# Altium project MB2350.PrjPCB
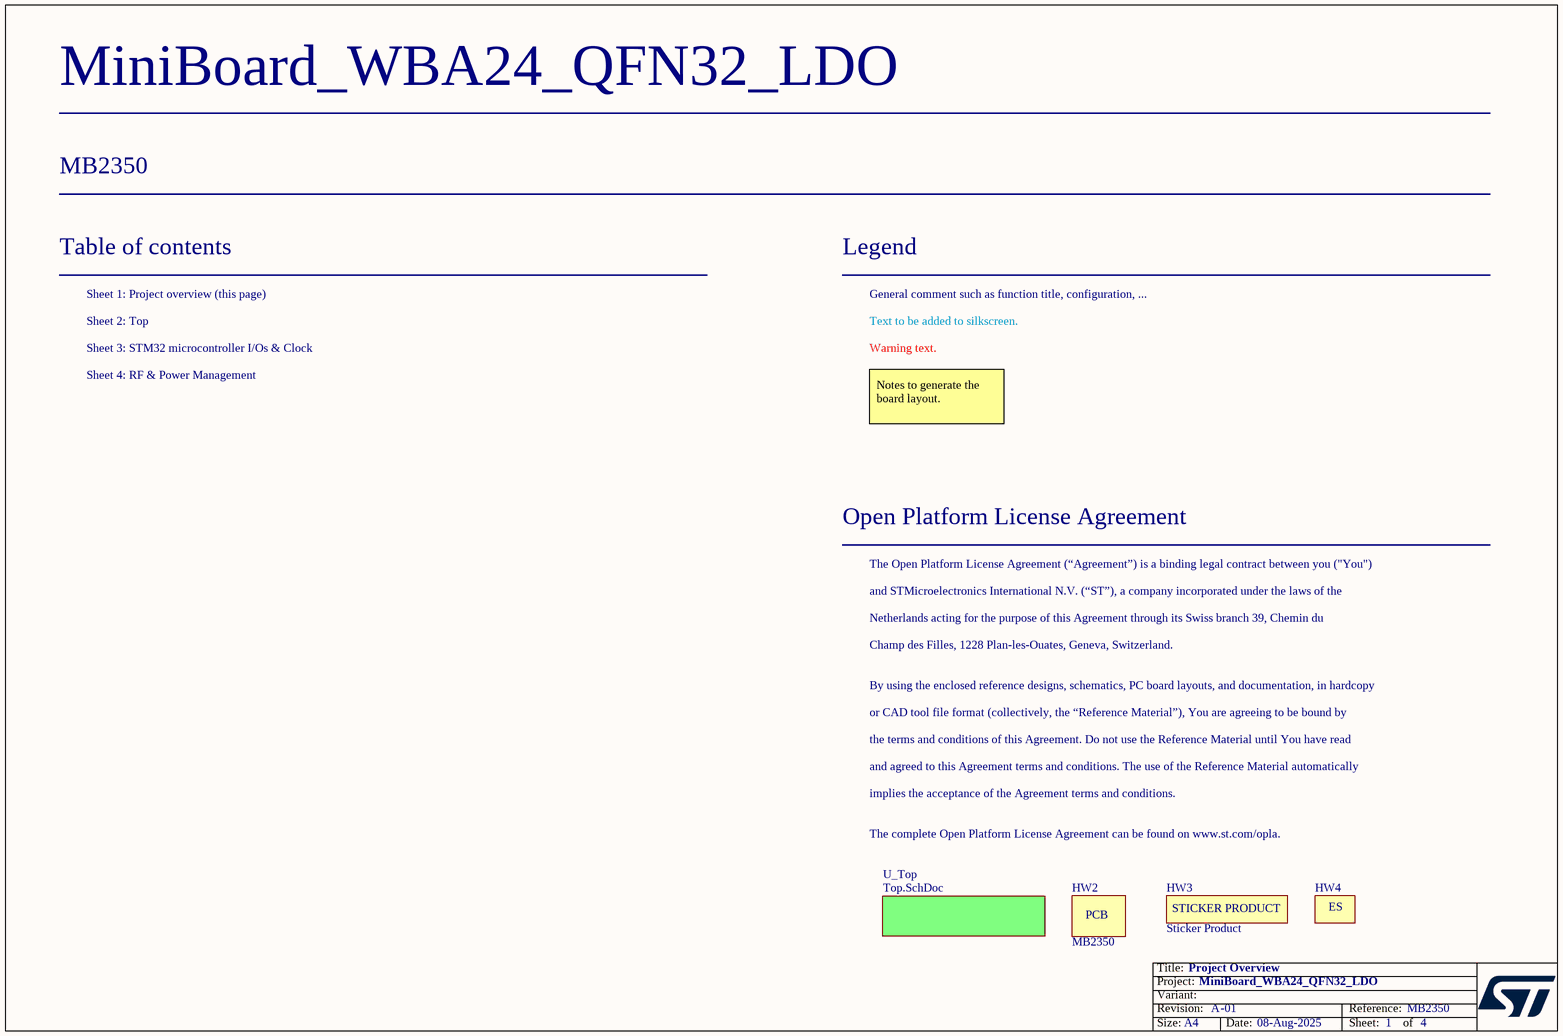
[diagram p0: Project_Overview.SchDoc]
Board_Assembly_Revision: 01; Board_Document_Date: 08-Aug-2025; Board_Name: MiniBoard_WBA24_QFN32_LDO; Board_PCB_Revision: A; Board_Reference: MB2350
4 sheets, 88 parts. Net scope: flat (ports and power ports of the same name join across sheets).
Board file: MB2350.PcbDoc
Sheets:
  Project_Overview.SchDoc
    U_Top = Top.SchDoc
      STM32 microcontroller I/Os & Clock = MCU.SchDoc
      RF & Power Management Schematic = RF&Power_Management.SchDoc

## Sheet Project_Overview.SchDoc: Project Overview
size A4; Date: Not used; ApprovedBy: Not used; CheckedBy: Not used; Author: Not used; CompanyName: STMicroelectronics; DrawnBy: Not used; Engineer: Not used; Organization: Not used; Address1: Not used; Address2: Not used; Address3: Not used; Address4: Not used; DocumentNumber: Not used; Revision: Not used; SheetNumber: 1; SheetTotal: 4

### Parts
HW2  value MB2350  (hidden comment: PCB)  (mechanical)
HW3  value Sticker Product  [STICKER_PRODUCT_25X9]  (hidden comment: STICKER_PRODUCT)  (no BOM)
HW4  STICKER_ES  [STICKER_ES_6X6]  (value not drawn)  (no BOM)

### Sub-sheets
U_Top = Top.SchDoc: no entries

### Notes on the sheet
- Table of contents
- Sheet 1: Project overview (this page)
- Legend
- General comment such as function title, configuration, ...
- Sheet 2: Top
- Sheet 3: STM32 microcontroller I/Os & Clock
- Sheet 4: RF & Power Management
- Text to be added to silkscreen.
- Warning text.
- Notes to generate the board layout.
- Open Platform License Agreement
- The Open Platform License Agreement (“Agreement”) is a binding legal contract between you ("You")
- and STMicroelectronics International N.V. (“ST”), a company incorporated under the laws of the
- Netherlands acting for the purpose of this Agreement through its Swiss branch 39, Chemin du
- Champ des Filles, 1228 Plan-les-Ouates, Geneva, Switzerland.
- By using the enclosed reference designs, schematics, PC board layouts, and documentation, in hardcopy
- or CAD tool file format (collectively, the “Reference Material”), You are agreeing to be bound by
- the terms and conditions of this Agreement. Do not use the Reference Material until You have read
- and agreed to this Agreement terms and conditions. The use of the Reference Material automatically
- implies the acceptance of the Agreement terms and conditions.
- The complete Open Platform License Agreement can be found on www.st.com/opla.

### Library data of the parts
HW2 = MCD-04883: PCB, MB2350 ,47mmx43mm, 4L2S, 1.6mm, standard, FR4; Part_Preference: Forbidden; Manufacturer: PLOTEC; ShowFields: YES; ID: 6999
HW3 = MCD-00547: Sticker product, 25x9mm; Part_Type: Misc; Part_Preference: Recommended; Component_Country_Of_Origin: Unknown; ShowFields: YES; ID: 3197
HW4 = MCD-00234: Sticker ES, 6x6mm; Part_Type: Misc; Part_Preference: Recommended; Component_Country_Of_Origin: Unknown; ShowFields: YES; ID: 2634

## Sheet Top.SchDoc: Top Schematic
size A4; Date: Not used; ApprovedBy: Not used; CheckedBy: Not used; Author: Not used; CompanyName: STMicroelectronics; DrawnBy: Not used; Engineer: Not used; Organization: Not used; Address1: Not used; Address2: Not used; Address3: Not used; Address4: Not used; DocumentNumber: Not used; Revision: Not used; SheetNumber: 2; SheetTotal: 4
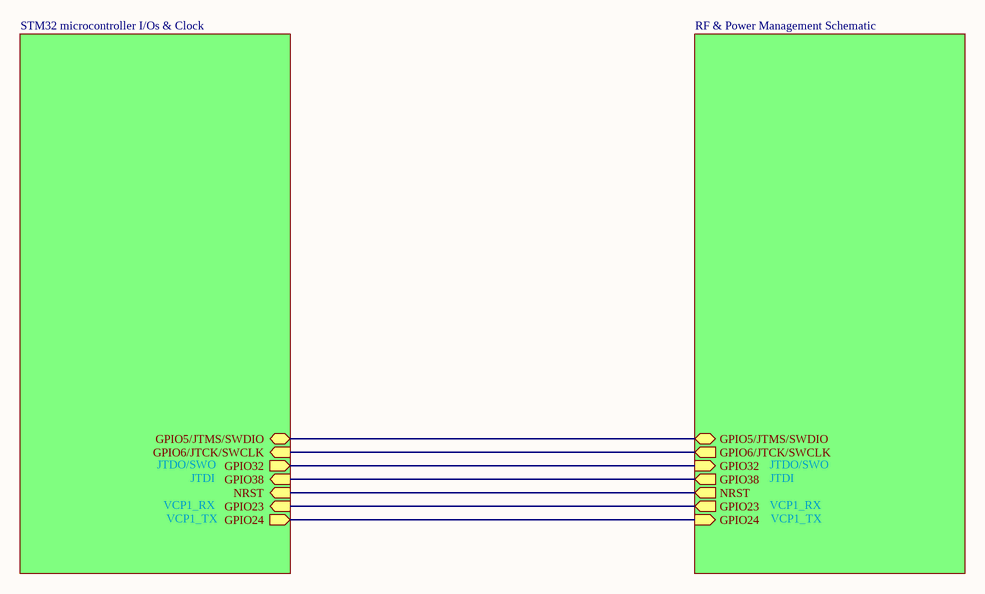
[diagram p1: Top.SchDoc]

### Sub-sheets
RF & Power Management Schematic = RF&Power_Management.SchDoc: GPIO5/JTMS/SWDIO (bidir), GPIO6/JTCK/SWCLK (out), GPIO32 (in), GPIO38 (out), NRST (out), GPIO23 (out), GPIO24 (in)
STM32 microcontroller I/Os & Clock = MCU.SchDoc: GPIO5/JTMS/SWDIO (bidir), GPIO6/JTCK/SWCLK (in), GPIO32 (out), GPIO38 (in), NRST (in), GPIO23 (in), GPIO24 (out)

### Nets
(unnamed): sheet STM32 microcontroller I/Os & Clock/GPIO5/JTMS/SWDIO, sheet RF & Power Management Schematic/GPIO5/JTMS/SWDIO
(unnamed): sheet STM32 microcontroller I/Os & Clock/GPIO6/JTCK/SWCLK, sheet RF & Power Management Schematic/GPIO6/JTCK/SWCLK  [a separate net that carries the same name]
(unnamed): sheet STM32 microcontroller I/Os & Clock/GPIO32, sheet RF & Power Management Schematic/GPIO32  [a separate net that carries the same name]
(unnamed): sheet STM32 microcontroller I/Os & Clock/GPIO38, sheet RF & Power Management Schematic/GPIO38  [a separate net that carries the same name]
(unnamed): sheet STM32 microcontroller I/Os & Clock/NRST, sheet RF & Power Management Schematic/NRST  [a separate net that carries the same name]
(unnamed): sheet STM32 microcontroller I/Os & Clock/GPIO23, sheet RF & Power Management Schematic/GPIO23  [a separate net that carries the same name]
(unnamed): sheet STM32 microcontroller I/Os & Clock/GPIO24, sheet RF & Power Management Schematic/GPIO24  [a separate net that carries the same name]

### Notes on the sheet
- JTDO/SWO
- VCP1_RX
- VCP1_TX
- JTDI

## Sheet MCU.SchDoc: STM32 microcontroller I/Os & Clock
size A4; Date: Not used; ApprovedBy: Not used; CheckedBy: Not used; Author: Not used; CompanyName: STMicroelectronics; DrawnBy: Not used; Engineer: Not used; Organization: Not used; Address1: Not used; Address2: Not used; Address3: Not used; Address4: Not used; DocumentNumber: Not used; Revision: Not used; SheetNumber: 3; SheetTotal: 4
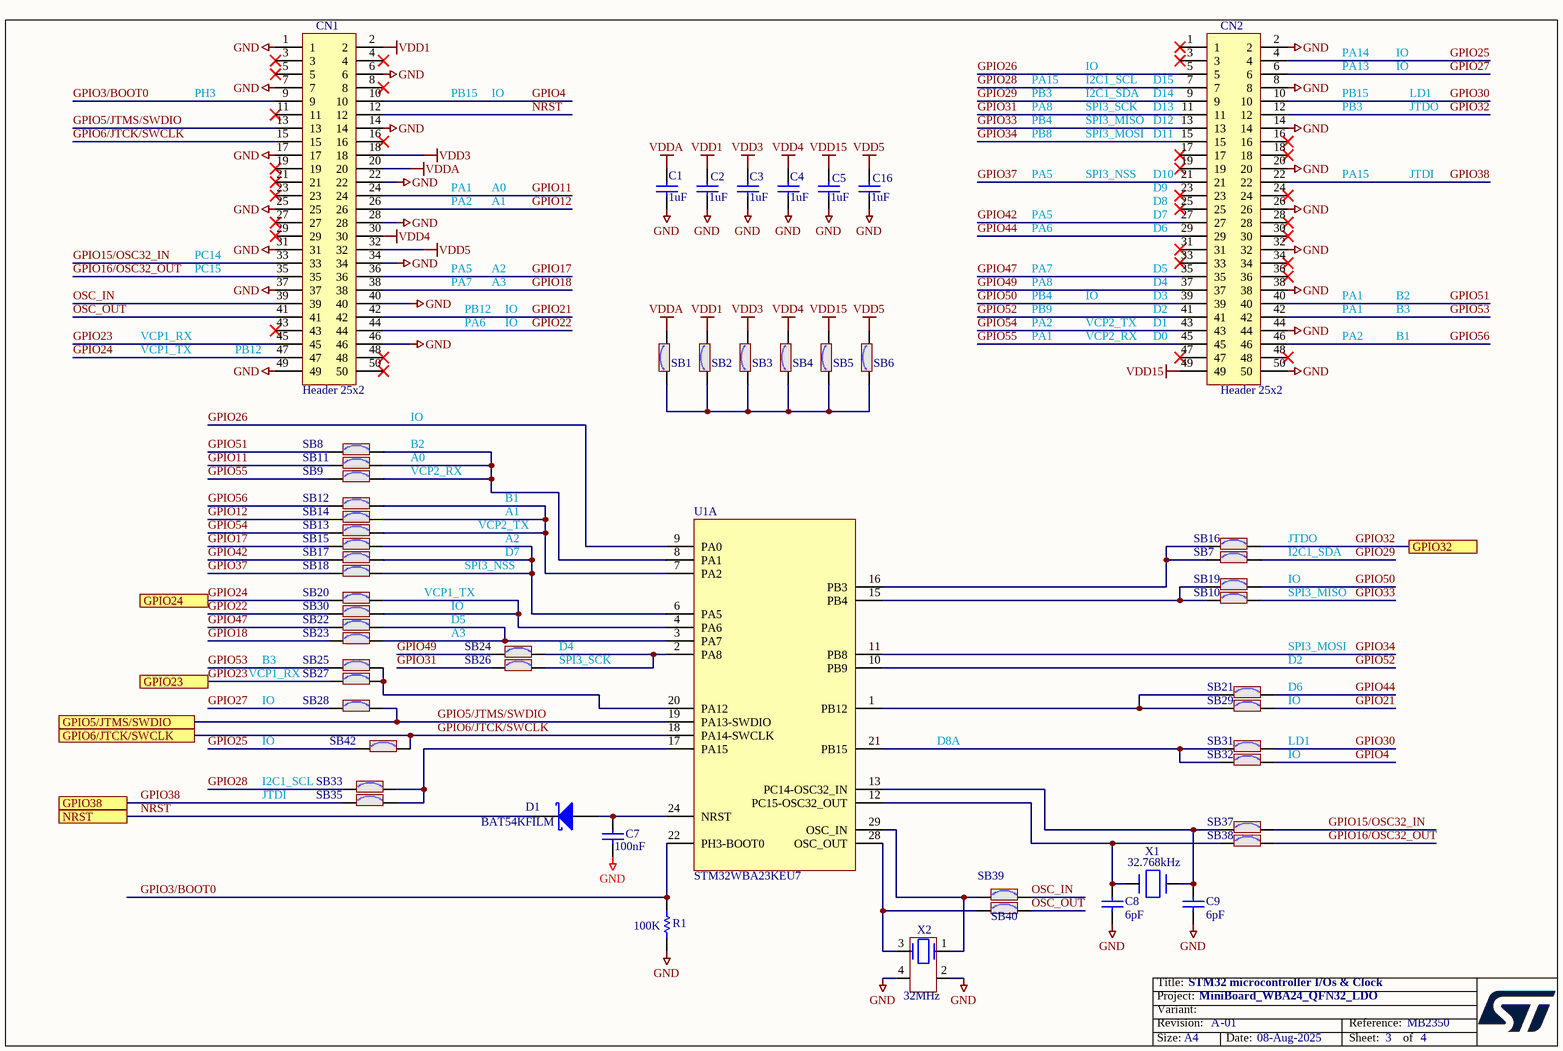
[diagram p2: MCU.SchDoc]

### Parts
C1  value 1uF  [C0402]  (hidden comment: Capacitor)
C2  value 1uF  [C0402]  (hidden comment: Capacitor)
C3  value 1uF  [C0402]  (hidden comment: Capacitor)
C4  value 1uF  [C0402]  (hidden comment: Capacitor)
C5  value 1uF  [C0402]  (hidden comment: Capacitor)
C7  value 100nF  [C0402]  (hidden comment: Capacitor)
C8  value 6pF  [C0402]  (hidden comment: Capacitor)
C9  value 6pF  [C0402]  (hidden comment: Capacitor)
C16  value 1uF  [C0402]  (hidden comment: Capacitor)
CN1  Header 25x2  [FTSH-125-02-L-DV]
CN2  Header 25x2  [FTSH-125-02-L-DV]
D1  value BAT54KFILM  [DIO_SOD523_1A_2K]  (hidden comment: SCHOTTKY_1A_2K)
R1  value 100K  [R0402]  (hidden comment: Resistor)
SB1  SB_ON  [SOLDER-BRIDGE_R0402-0R]  (value not drawn)
SB2  SB_ON  [SOLDER-BRIDGE_R0402-0R]  (value not drawn)
SB3  SB_ON  [SOLDER-BRIDGE_R0402-0R]  (value not drawn)
SB4  SB_ON  [SOLDER-BRIDGE_R0402-0R]  (value not drawn)
SB5  SB_ON  [SOLDER-BRIDGE_R0402-0R]  (value not drawn)
SB6  SB_ON  [SOLDER-BRIDGE_R0402-0R]  (value not drawn)
SB7  SB_ON  [SOLDER-BRIDGE_R0402-0R]  (value not drawn)
SB8  SB_ON  [SOLDER-BRIDGE_R0402-0R]  (value not drawn)
SB9  SB_ON  [SOLDER-BRIDGE_R0402-0R]  (value not drawn)
SB10  SB_ON  [SOLDER-BRIDGE_R0402-0R]  (value not drawn)
SB11  SB_ON  [SOLDER-BRIDGE_R0402-0R]  (value not drawn)
SB12  SB_ON  [SOLDER-BRIDGE_R0402-0R]  (value not drawn)
SB13  SB_ON  [SOLDER-BRIDGE_R0402-0R]  (value not drawn)
SB14  SB_ON  [SOLDER-BRIDGE_R0402-0R]  (value not drawn)
SB15  SB_ON  [SOLDER-BRIDGE_R0402-0R]  (value not drawn)
SB16  SB_ON  [SOLDER-BRIDGE_R0402-0R]  (value not drawn)
SB17  SB_ON  [SOLDER-BRIDGE_R0402-0R]  (value not drawn)
SB18  SB_ON  [SOLDER-BRIDGE_R0402-0R]  (value not drawn)
SB19  SB_ON  [SOLDER-BRIDGE_R0402-0R]  (value not drawn)
SB20  SB_ON  [SOLDER-BRIDGE_R0402-0R]  (value not drawn)
SB21  SB_ON  [SOLDER-BRIDGE_R0402-0R]  (value not drawn)
SB22  SB_ON  [SOLDER-BRIDGE_R0402-0R]  (value not drawn)
SB23  SB_ON  [SOLDER-BRIDGE_R0402-0R]  (value not drawn)
SB24  SB_ON  [SOLDER-BRIDGE_R0402-0R]  (value not drawn)
SB25  SB_ON  [SOLDER-BRIDGE_R0402-0R]  (value not drawn)
SB26  SB_ON  [SOLDER-BRIDGE_R0402-0R]  (value not drawn)
SB27  SB_ON  [SOLDER-BRIDGE_R0402-0R]  (value not drawn)
SB28  SB_ON  [SOLDER-BRIDGE_R0402-0R]  (value not drawn)
SB29  SB_ON  [SOLDER-BRIDGE_R0402-0R]  (value not drawn)
SB30  SB_ON  [SOLDER-BRIDGE_R0402-0R]  (value not drawn)
SB31  SB_ON  [SOLDER-BRIDGE_R0402-0R]  (value not drawn)
SB32  SB_ON  [SOLDER-BRIDGE_R0402-0R]  (value not drawn)
SB33  SB_ON  [SOLDER-BRIDGE_R0402-0R]  (value not drawn)
SB35  SB_ON  [SOLDER-BRIDGE_R0402-0R]  (value not drawn)
SB37  SB_ON  [SOLDER-BRIDGE_R0402-0R]  (value not drawn)
SB38  SB_ON  [SOLDER-BRIDGE_R0402-0R]  (value not drawn)
SB39  SB_ON  [SOLDER-BRIDGE_R0402-0R]  (value not drawn)
SB40  SB_ON  [SOLDER-BRIDGE_R0402-0R]  (value not drawn)
SB42  SB_ON  [SOLDER-BRIDGE_R0402-0R]  (value not drawn)
U1  value STM32WBA23KEU7  [ICC_UFQFPN32-EPAD_5X5_P050]  (hidden comment: IC_STM32WBA23KEU7)  (part A of 3)
X1  value 32.768kHz  [CRY_NX1610SE_2P]  (hidden comment: XTAL_2_PINS)
X2  value 32MHz  [CRY_NX1612SA_4P]  (hidden comment: XTAL_4_PINS)

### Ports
GPIO5/JTMS/SWDIO, GPIO6/JTCK/SWCLK, GPIO23, GPIO24, GPIO32, GPIO38, NRST

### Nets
GND: C1.1 C2.1 C3.1 C4.1 C5.1 C7.1 C8.1 C9.1 C16.1 CN1.1 CN1.6 CN1.7 CN1.14 CN1.17 CN1.22 CN1.25 CN1.28 CN1.31 CN1.34 CN1.37 CN1.40 CN1.46 CN1.49 CN2.2 CN2.8 CN2.14 CN2.20 CN2.26 CN2.32 CN2.38 CN2.44 CN2.50 R1.2 X2.2 X2.4
VDD1: C2.2 CN1.2 SB2.2
VDD3: C3.2 CN1.18 SB3.2
VDD4: C4.2 CN1.30 SB4.2
VDD5: C16.2 CN1.32 SB6.2
VDD15: C5.2 CN2.49 SB5.2
VDDA: C1.2 CN1.20 SB1.2
GPIO3/BOOT0: CN1.9 R1.1 U1.22(PH3-BOOT0)
GPIO4: CN1.10 SB32.2
GPIO5/JTMS/SWDIO: CN1.13 SB28.2 U1.19(PA13-SWDIO) ; port GPIO5/JTMS/SWDIO
GPIO6/JTCK/SWCLK: CN1.15 SB42.2 U1.18(PA14-SWCLK) ; port GPIO6/JTCK/SWCLK
GPIO11: CN1.24 SB11.1
GPIO12: CN1.26 SB14.1
GPIO15/OSC32_IN: CN1.33 SB37.2
GPIO16/OSC32_OUT: CN1.35 SB38.2
GPIO17: CN1.36 SB15.1
GPIO18: CN1.38 SB23.1
GPIO21: CN1.42 SB29.2
GPIO22: CN1.44 SB30.1
GPIO23: CN1.45 SB27.1 ; port GPIO23
GPIO24: CN1.47 SB20.1 ; port GPIO24
GPIO25: CN2.4 SB42.1
GPIO26: CN2.5 U1.9(PA0)
GPIO27: CN2.6 SB28.1
GPIO28: CN2.7 SB33.1
GPIO29: CN2.9 SB7.2
GPIO30: CN2.10 SB31.2
GPIO31: CN2.11 SB26.1
GPIO32: CN2.12 SB16.2 ; port GPIO32
GPIO33: CN2.13 SB10.2
GPIO34: CN2.15 U1.11(PB8)
GPIO37: CN2.21 SB18.1
GPIO38: CN2.22 SB35.1 ; port GPIO38
GPIO42: CN2.27 SB17.1
GPIO44: CN2.29 SB21.2
GPIO47: CN2.35 SB22.1
GPIO49: CN2.37 SB24.1
GPIO50: CN2.39 SB19.2
GPIO51: CN2.40 SB8.1
GPIO52: CN2.41 U1.10(PB9)
GPIO53: CN2.42 SB25.1
GPIO54: CN2.43 SB13.1
GPIO55: CN2.45 SB9.1
GPIO56: CN2.46 SB12.1
NRST: CN1.12 D1.2(K) ; port NRST
OSC_IN: CN1.39 SB39.2
OSC_OUT: CN1.41 SB40.2
NetC7_2: C7.2 D1.1(A) U1.24(NRST)
NetC8_2: C8.2 SB38.1 U1.12(PC15-OSC32_OUT) X1.2(X2)
NetC9_2: C9.2 SB37.1 U1.13(PC14-OSC32_IN) X1.1(X1)
NetSB1_1: SB1.1 SB2.1 SB3.1 SB4.1 SB5.1 SB6.1
NetSB7_1: SB7.1 SB16.1 U1.16(PB3)
NetSB8_2: SB8.2 SB9.2 SB11.2 U1.8(PA1)
NetSB10_1: SB10.1 SB19.1 U1.15(PB4)
NetSB12_2: SB12.2 SB13.2 SB14.2 U1.7(PA2)
NetSB15_2: SB15.2 SB17.2 SB18.2 U1.6(PA5)
NetSB20_2: SB20.2 SB30.2 U1.4(PA6)
NetSB21_1: SB21.1 SB29.1 U1.1(PB12)
NetSB22_2: SB22.2 SB23.2 U1.3(PA7)
NetSB24_2: SB24.2 SB26.2 U1.2(PA8)
NetSB25_2: SB25.2 SB27.2 U1.20(PA12)
NetSB31_1: SB31.1 SB32.1 U1.21(PB15)
NetSB33_2: SB33.2 SB35.2 U1.17(PA15)
NetSB39_1: SB39.1 U1.29(OSC_IN) X2.1
NetSB40_1: SB40.1 U1.28(OSC_OUT) X2.3

Not connected (* = marked no-connect by the designer): CN1 3* 4* 5* 8* 11* 16* 19* 21* 23* 27* 29* 43* 48* 50*; CN2 1* 3* 16* 17* 18* 19* 23* 24* 25* 28* 30* 31* 33* 34* 36* 47* 48*

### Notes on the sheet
- PA14
- IO
- PH3
- PB15
- PB3
- PA15
- PB4
- PA8
- SPI3_SCK
- I2C1_SCL
- I2C1_SDA
- SPI3_MISO
- (near CN2) D13
- (near CN2) D14
- (near CN2) D15
- (near CN2) D12
- PA13
- JTDO
- LD1
- PA1
- A0
- PA5
- PB8
- SPI3_NSS
- SPI3_MOSI
- (near CN2) D11
- (near CN2) D10
- (near CN2) D9
- JTDI
- PC14
- PA2
- A1
- PA6
- (near CN2) D8
- (near CN2) D7
- (near CN2) D6
- PC15
- PA7
- PB12
- A2
- A3
- PB9
- VCP2_TX
- (near CN2) D1
- (near CN2) D5
- (near CN2) D4
- (near CN2) D3
- (near CN2) D2
- B2
- B3
- VCP1_RX
- VCP1_TX
- (near CN1) PB12
- VCP2_RX
- (near CN2) D0
- B1
- D7
- D5
- D4
- D2
- D6
- D8A

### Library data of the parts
C1-C5 C16 = MCD-01722: Capacitor, MLCC, 1uF, 10V, X5R, +/-10%, 0402, T=0.5mm; Part_Preference: Recommended; Manufacturer: YAGEO; Manufacturer_Part_Number: CC0402KRX5R6BB105; Component_Country_Of_Origin: China
C7 = MCD-00006: Capacitor, MLCC, 100nF, 16V, X7R, +/-10%, 0402, T=0.5mm; Manufacturer_Part_Number: CC0402KRX7R7BB104; Manufacturer: YAGEO; Alternate_Manufacturer_Part_Number: GCM155R71C104KA55D; Alternate_Manufacturer: MURATA; Part_Preference: Recommended; Order_Code_RS: 616-9701
C8 C9 = MCD-03185: Capacitor, MLCC, 6pF, 50V, C0G/NP0, +/-0,25pF, 0402, T=0.5mm; Part_Preference: Recommended; Manufacturer: MURATA; Manufacturer_Part_Number: GJM1555C1H6R0CB01; Order_Code_RS: 170-6040; Component_Country_Of_Origin: Singapore; ShowFields: YES; ID: 5301
CN1 CN2 = MCD-02746: Header, 25x2, 1.27mm, VR, SMD, T=4.83mm; Part_Type: Connector; Part_Preference: Recommended; Manufacturer: SAMTEC; Partial_Alternate_Internal_Part_Number: MCD-03741; ShowFields: YES; ID: 4858; Component_Country_Of_Origin: China, Costa Rica, Malaysia, USA, Vietnam
D1 = MCD-01677: Small signal Schottky diodes; Part_Type: Diode; Manufacturer: STMICROELECTRONICS; BMS_Part_Number: 9151123; Part_Preference: Recommended; Manufacturer_HQ_COO: EU
R1 = MCD-00059: Resistor, 100K, 0402, +/-1%, 1/16W; Part_Preference: Recommended; Manufacturer: YAGEO; Manufacturer_Part_Number: RC0402FR-07100KL; Component_Country_Of_Origin: China
SB1-SB33 SB35 SB37-SB40 SB42 = MCD-01618: Solder Bridge 0402 ON; Part_Type: Misc; Part_Preference: Recommended; Manufacturer: YAGEO; Manufacturer_Part_Number: RC0402JR-070RL; Order_Code_RS: 618-5804; Component_Country_Of_Origin: China
U1 = MCD-04382: MCU, ARM Cortex-M33 32-bit, 512KB Flash, 96KB RAM, Crypto; Part_Type: IC; Part_Preference: Recommended; Manufacturer: STMICROELECTRONICS; Component_Country_Of_Origin: Unknown; ShowFields: YES; ID: 6498
X1 = MCD-02579: Crystal, 32.768kHz, 6pF, +/-20ppm, 70KR, 1.6x1mm; Part_Type: Crystal_Osc; Part_Preference: Recommended; Manufacturer: NDK; Manufacturer_Part_Number: NX1610SE-32.768KHZ-EXS00A-MU01501
X2 = MCD-02578: Crystal, 32MHz, 8pF, +/-10ppm, 40R, 1612(metric), T=0.3mm; Part_Type: Crystal_Osc; Part_Preference: Recommended; Manufacturer: NDK; Manufacturer_Part_Number: NX1612SA-32MHZ-EXS00A-CS09166

## Sheet RF&Power_Management.SchDoc: RF & Power Management Schematic
size A4; Date: Not used; ApprovedBy: Not used; CheckedBy: Not used; Author: Not used; CompanyName: STMicroelectronics; DrawnBy: Not used; Engineer: Not used; Organization: Not used; Address1: Not used; Address2: Not used; Address3: Not used; Address4: Not used; DocumentNumber: Not used; Revision: Not used; SheetNumber: 4; SheetTotal: 4
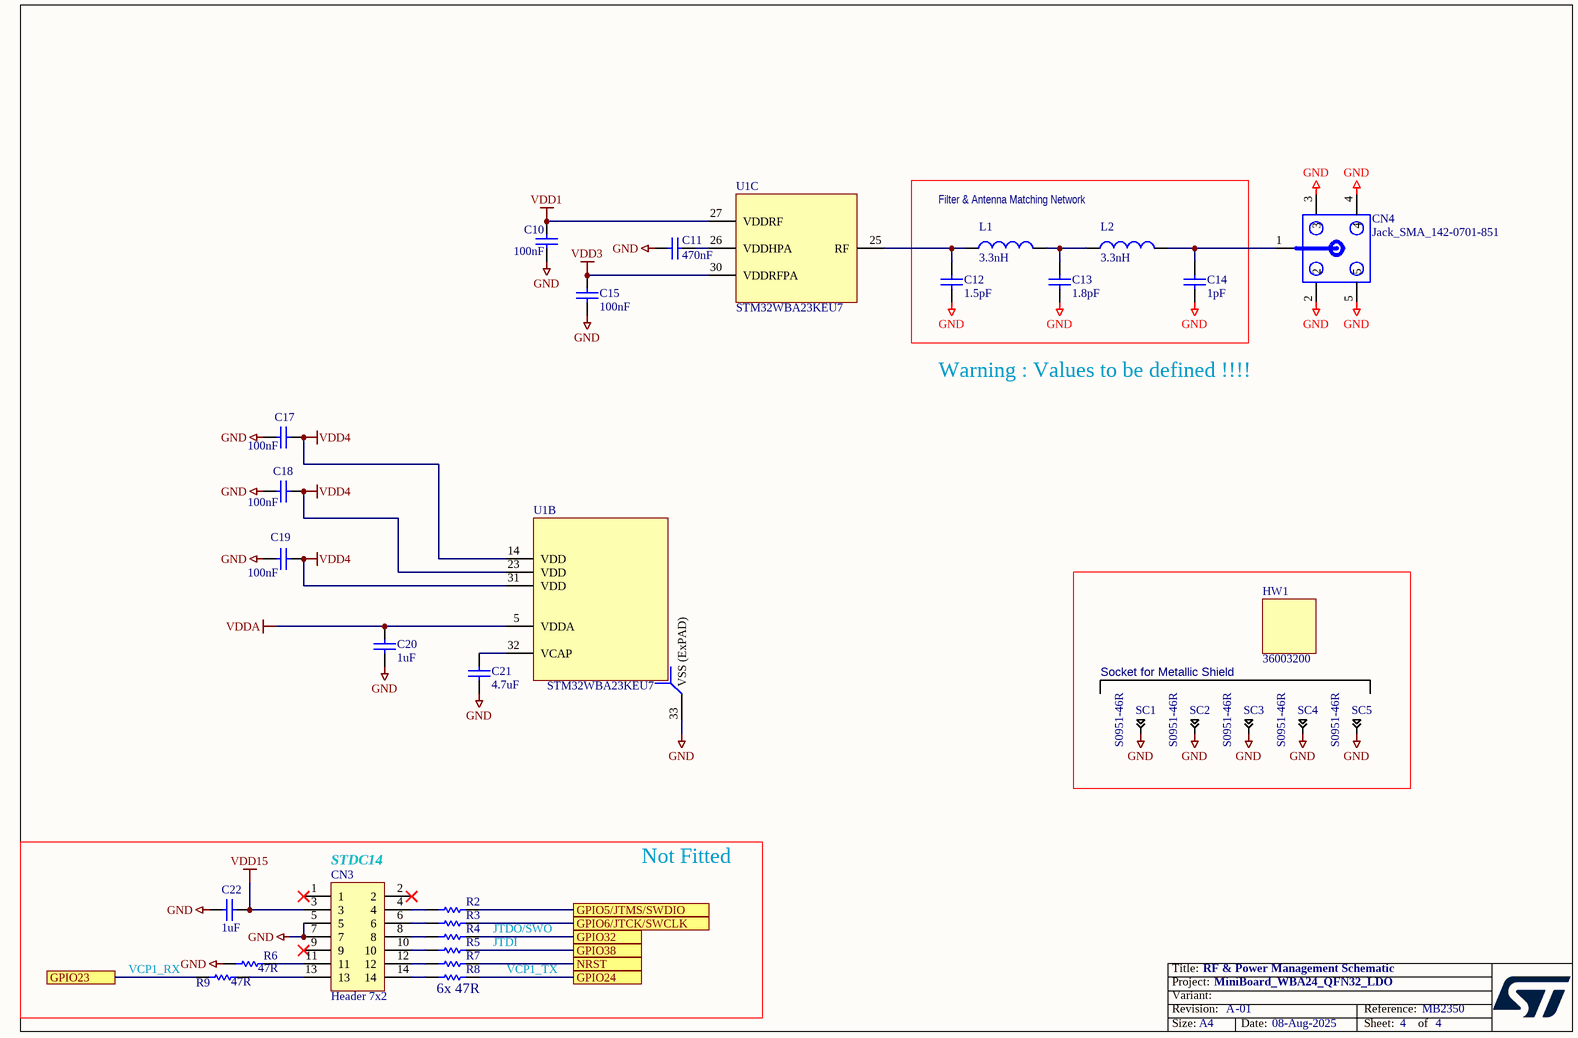
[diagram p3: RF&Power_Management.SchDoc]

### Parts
C10  value 100nF  [C0402]  (hidden comment: Capacitor)
C11  value 470nF  [C0603]  (hidden comment: Capacitor)
C12  value 1.5pF  [C0402]  (hidden comment: Capacitor)
C13  value 1.8pF  [C0402]  (hidden comment: Capacitor)
C14  value 1pF  [C0402]  (hidden comment: Capacitor)
C15  value 100nF  [C0402]  (hidden comment: Capacitor)
C17  value 100nF  [C0402]  (hidden comment: Capacitor)
C18  value 100nF  [C0402]  (hidden comment: Capacitor)
C19  value 100nF  [C0402]  (hidden comment: Capacitor)
C20  value 1uF  [C0402]  (hidden comment: Capacitor)
C21  value 4.7uF  [C0603_H0P8]  (hidden comment: Capacitor)
C22  value 1uF  [C0603]  (hidden comment: Capacitor)
CN3  Header 7x2  [CON_SAMTEC_FTSH-107-01-L-DV-K-A]
CN4  value Jack_SMA_142-0701-851  [CON_SMA-RF_CINCH_142-0701-851]  (hidden comment: SMA-J-P-H-ST-EM1)
HW1  value 36003200  [SHIELD_WURTH_36003200_21P8X21P8]  (hidden comment: Shield Cover)
L1  value 3.3nH  [C0402]  (hidden comment: Inductor)
L2  value 3.3nH  [C0402]  (hidden comment: Inductor)
R2  Resistor  [R0402]  (value not drawn)
R3  Resistor  [R0402]  (value not drawn)
R4  Resistor  [R0402]  (value not drawn)
R5  Resistor  [R0402]  (value not drawn)
R6  value 47R  [R0402]  (hidden comment: Resistor)
R7  Resistor  [R0402]  (value not drawn)
R8  Resistor  [R0402]  (value not drawn)
R9  value 47R  [R0402]  (hidden comment: Resistor)
SC1  value S0951-46R  [CLIP_HARWIN_S0951-46R]  (hidden comment: Shield-clip_S0951-46R)
SC2  value S0951-46R  [CLIP_HARWIN_S0951-46R]  (hidden comment: Shield-clip_S0951-46R)
SC3  value S0951-46R  [CLIP_HARWIN_S0951-46R]  (hidden comment: Shield-clip_S0951-46R)
SC4  value S0951-46R  [CLIP_HARWIN_S0951-46R]  (hidden comment: Shield-clip_S0951-46R)
SC5  value S0951-46R  [CLIP_HARWIN_S0951-46R]  (hidden comment: Shield-clip_S0951-46R)
U1  value STM32WBA23KEU7  [ICC_UFQFPN32-EPAD_5X5_P050]  (hidden comment: IC_STM32WBA23KEU7)  (parts B,C of 3)

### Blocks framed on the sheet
Filter & Antenna Matching Network: C12-C14 L1 L2
Socket for Metallic Shield: HW1 SC1-SC5
Not Fitted: C22 CN3 R2-R9

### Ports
GPIO5/JTMS/SWDIO, GPIO6/JTCK/SWCLK, GPIO23, GPIO24, GPIO32, GPIO38, NRST

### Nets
GND: C10.2 C11.1 C12.1 C13.1 C14.1 C15.2 C17.2 C18.2 C19.2 C20.1 C21.1 C22.1 CN3.5 CN3.7 CN4.2 CN4.3 CN4.4 CN4.5 R6.1 SC1.1 SC2.1 SC3.1 SC4.1 SC5.1 U1.33(VSS_(ExPAD))
VDD1: C10.1 U1.27(VDDRF)
VDD3: C15.1 U1.30(VDDRFPA)
VDD4: C17.1 C18.1 C19.1 U1.14(VDD) U1.23(VDD) U1.31(VDD)
VDD15: C22.2 CN3.3
VDDA: C20.2 U1.5(VDDA)
GPIO5/JTMS/SWDIO: R2.2 ; port GPIO5/JTMS/SWDIO
GPIO6/JTCK/SWCLK: R3.2 ; port GPIO6/JTCK/SWCLK
GPIO23: R9.1 ; port GPIO23
GPIO24: R8.2 ; port GPIO24
GPIO32: R4.2 ; port GPIO32
GPIO38: R5.2 ; port GPIO38
NRST: R7.2 ; port NRST
NetC11_2: C11.2 U1.26(VDDHPA)
NetC12_2: C12.2 L1.1 U1.25(RF)
NetC13_2: C13.2 L1.2 L2.1
NetC14_2: C14.2 CN4.1 L2.2
NetC21_2: C21.2 U1.32(VCAP)
NetCN3_4: CN3.4 R2.1
NetCN3_6: CN3.6 R3.1
NetCN3_8: CN3.8 R4.1
NetCN3_10: CN3.10 R5.1
NetCN3_11: CN3.11 R6.2
NetCN3_12: CN3.12 R7.1
NetCN3_13: CN3.13 R9.2
NetCN3_14: CN3.14 R8.1

Not connected (* = marked no-connect by the designer): CN3 1* 2* 9*

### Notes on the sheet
- Warning : Values to be defined !!!!
- (near CN3) STDC14
- (near R9) VCP1_RX
- JTDI
- JTDO/SWO
- VCP1_TX
- (near R8) 6x 47R

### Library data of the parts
C10 C15 C17-C19 = MCD-00006: as C7 on sheet MCU
C11 = MCD-01006: Capacitor, MLCC, 470nF, 16V, X7R, +/-10%, 0603, T=0.8mm; BMS_Part_Number: 9142003; Part_Preference: Recommended; Manufacturer: YAGEO; Manufacturer_Part_Number: CC0603KRX7R7BB474; Order_Code_RS: 200-6576; Component_Country_Of_Origin: China
C12 = MCD-02994: Capacitor, MLCC, 1.5pF, 50V, C0G, +/-0.25pF, 0402, T=0.5mm; Part_Preference: Recommended; Manufacturer: MURATA; Manufacturer_Part_Number: GRM1555C1H1R5CA01; Component_Country_Of_Origin: Japan°; ShowFields: YES; ID: 5110
C13 = MCD-02995: Capacitor, MLCC, 1.8pF, 50V, C0G, +/-0.25pF, 0402, T=0.5mm; Part_Preference: Recommended; Manufacturer: MURATA; Manufacturer_Part_Number: GRM1555C1H1R8CA01; Order_Code_RS: 723-5357; Component_Country_Of_Origin: Japan°; ShowFields: YES; ID: 5111
C14 = MCD-03045: Capacitor, MLCC, 1.0pF, 50V, C0G, +/-0.25pF, 0402, T=0.5mm; Part_Preference: Recommended; Manufacturer: MURATA; Manufacturer_Part_Number: GRM1555C1H1R0CA01; ShowFields: YES; ID: 5161
C20 = MCD-01722: as C1 on sheet MCU
C21 = MCD-01721: Capacitor, MLCC, 4.7uF, 10V, X5R, +/-10%, 0603, T=0.8mm; Part_Preference: Recommended; Manufacturer: YAGEO; Manufacturer_Part_Number: CC0603KRX5R6BB475; Component_Country_Of_Origin: China
C22 = MCD-00010: Capacitor, MLCC, 1uF, 16V, X5R, 10%, 0603, T=0,8mm; Manufacturer_Part_Number: CC0603KRX5R7BB105; Manufacturer: YAGEO; Provided_By: Subcon; Initial_Board_Reference: MB1274
CN3 = MCD-01531: Header, 7x2, 1.27mm, VR, T=5.97mm, FTSH series STDC14 without Alignment Pin; Part_Type: Connector; Part_Preference: Recommended; Manufacturer: SAMTEC; Manufacturer_Part_Number: FTSH-107-01-L-DV-K; Order_Code_RS: 179-9021; Component_Country_Of_Origin: China, Costa Rica, Malaysia, United States, Vietnam
CN4 = MCD-02072: Jack_SMA, VR, PCB edge, 50R, T=7.92mm; Part_Type: Connector; Part_Preference: Recommended; Manufacturer: JOHNSON; Manufacturer_Part_Number: 142-0701-851; Order_Code_RS: 885-7532; Component_Country_Of_Origin: United States; ShowFields: YES; ID: 4172
HW1 = MCD-04686: RF Shield cover, 21.5x21.5x3.3mm; Part_Type: Misc; Part_Preference: Recommended; Manufacturer: WURTH ELEKTRONIK; Order_Code_RS: 773-7282; ShowFields: YES; ID: 6802; Component_Country_Of_Origin: Germany°
L1 L2 = MCD-03001: Inductor, 3.3nH, +/-0.3nH, 800 mA, 0.125Ohm, 0402, T=0.5mm; Part_Preference: Recommended; Manufacturer: MURATA; Manufacturer_Part_Number: LQG15HS3N3S02; Component_Country_Of_Origin: Japan°; ShowFields: YES; ID: 5117
R2-R9 = MCD-00481: Resistor,47R,0402,1%,1/16W; Manufacturer_Part_Number: RC0402FR-0747RL; Manufacturer: YAGEO; Provided_By: Subcon
SC1-SC5 = MCD-01587: shield clip Harwin S0951-46R to fix RF shielded cavity; Part_Type: Misc; Part_Preference: Recommended; Component_Country_Of_Origin: South Korea
U1 = MCD-04382: as U1 on sheet MCU

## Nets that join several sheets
GND: MCU (35 pins), RF&Power_Management (25 pins)
VDD1: MCU (C2.2 CN1.2 SB2.2), RF&Power_Management (C10.1 U1.27)
VDD3: MCU (C3.2 CN1.18 SB3.2), RF&Power_Management (C15.1 U1.30)
VDD4: MCU (C4.2 CN1.30 SB4.2), RF&Power_Management (6 pins)
VDD15: MCU (C5.2 CN2.49 SB5.2), RF&Power_Management (C22.2 CN3.3)
VDDA: MCU (C1.2 CN1.20 SB1.2), RF&Power_Management (C20.2 U1.5)
GPIO5/JTMS/SWDIO: MCU (CN1.13 SB28.2 U1.19), RF&Power_Management (R2.2)
GPIO6/JTCK/SWCLK: MCU (CN1.15 SB42.2 U1.18), RF&Power_Management (R3.2)
GPIO23: MCU (CN1.45 SB27.1), RF&Power_Management (R9.1)
GPIO24: MCU (CN1.47 SB20.1), RF&Power_Management (R8.2)
GPIO32: MCU (CN2.12 SB16.2), RF&Power_Management (R4.2)
GPIO38: MCU (CN2.22 SB35.1), RF&Power_Management (R5.2)
NRST: MCU (CN1.12 D1.2), RF&Power_Management (R7.2)

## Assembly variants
WBA23KE: not fitted C1 C2 C3 C4 C5 C16 C22 CN3 R2 R3 R4 R5 R6 R7 R8 R9 SB1 SB2 SB3 SB4 SB5 SB6 SB8 SB9 SB12 SB13 SB15 SB16 SB17 SB19 SB22 SB24 SB25 SB28 SB29 SB30 SB32 SB35 SB37 SB38 SB39 SB40 SB42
